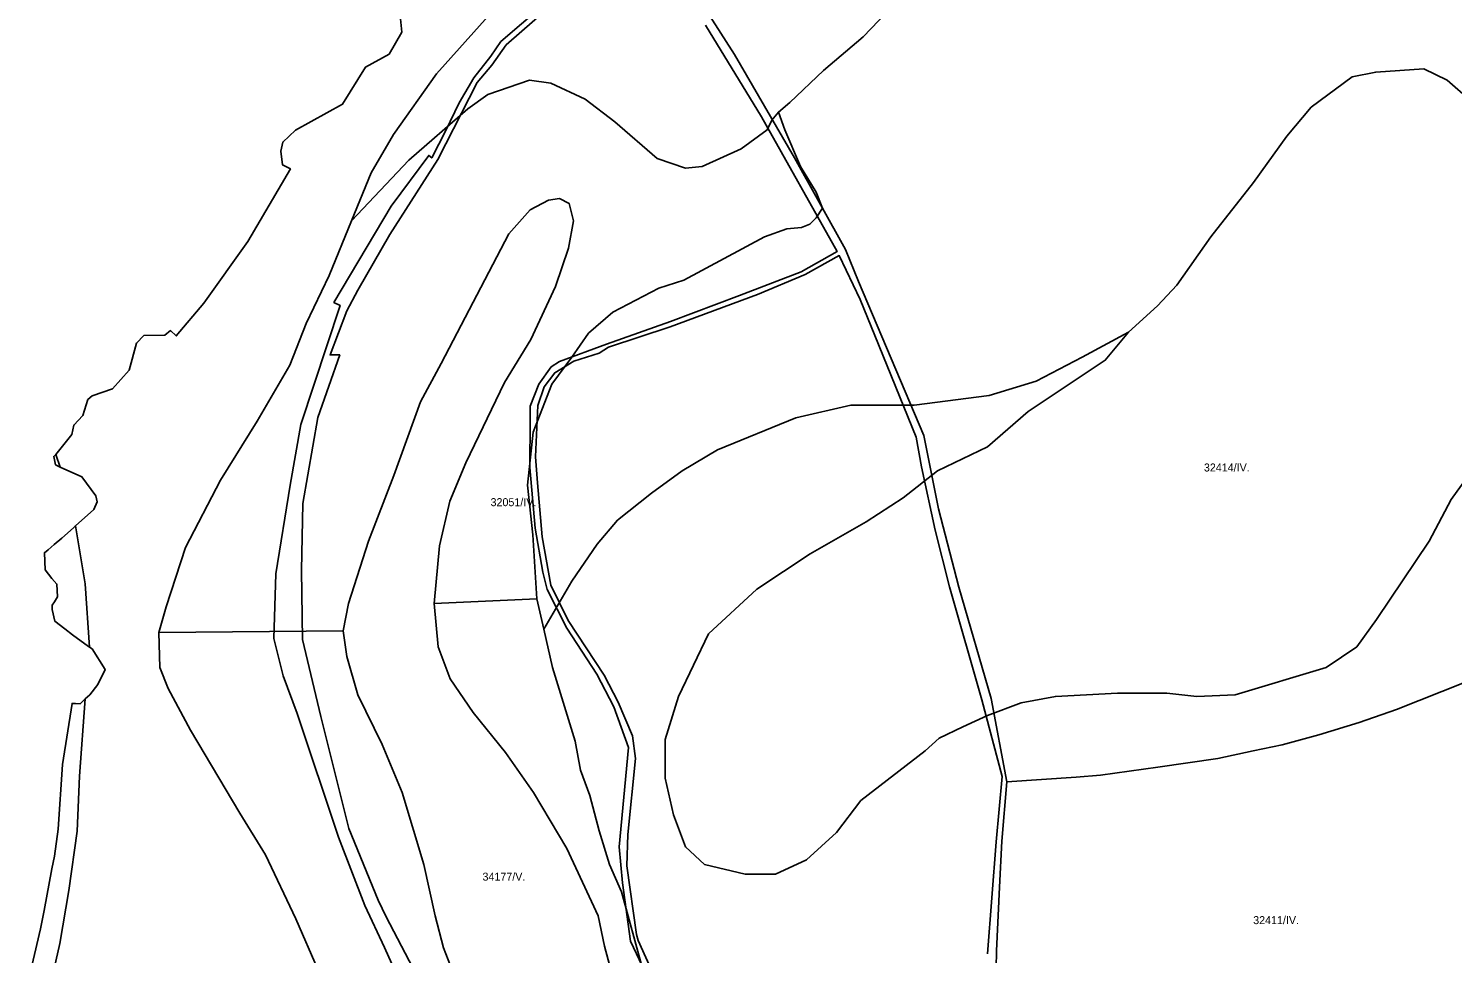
# Model space of a CAD drawing. Extents: x -532083 to -529270, y -1180561 to -1176456.
# Drawn here: x -532029 to -531139, y -1177920 to -1177342 of the extents above; entities that cross this region are included whole.
import ezdxf

# ---------------------------------------------------------------- set-up
doc = ezdxf.new("R2010")
doc.units = 0
for name, color, linetype in [('95560013', 7, 'Continuous'), ('95610013', 7, 'Continuous'), ('95660013', 7, 'Continuous')]:
    doc.layers.add(name, color=color, linetype=linetype)

msp = doc.modelspace()

# ---------------------------------------------------------------- linework, layer by layer
at = {"layer": '95560013'}
for points in [[(-531118.2913, -1177744.82245), (-531146.1423, -1177755.99745), (-531174.2873, -1177767.17245), (-531197.7413, -1177775.40645), (-531222.9543, -1177783.05245), (-531245.8213, -1177789.22745), (-531263.9983, -1177793.05045), (-531285.9863, -1177797.75545), (-531323.4343, -1177803.10345), (-531359.4253, -1177808.17745), (-531374.6003, -1177809.54345), (-531417.7903, -1177812.47045), (-531427.6483, -1177760.34245), (-531447.9583, -1177690.85545), (-531460.6533, -1177641.74245), (-531469.7043, -1177596.00345), (-531510.4973, -1177499.76545), (-531518.6553, -1177479.79745), (-531550.5493, -1177422.47345), (-531588.0313, -1177358.07445), (-531610.2983, -1177323.08245)], [(-532019.5363, -1177957.43845), (-532009.5583, -1177913.42645), (-532004.0573, -1177880.31745), (-531998.8613, -1177843.22345), (-531997.3333, -1177808.88745), (-531993.8613, -1177760.60945), (-531990.9163, -1177758.09745), (-531985.9083, -1177751.59745), (-531981.3223, -1177742.26745), (-531989.5113, -1177729.19145), (-531991.0143, -1177728.18545), (-531993.8163, -1177688.61945), (-531999.9123, -1177652.38745), (-531988.2743, -1177642.14645), (-531986.3353, -1177637.53845), (-531987.0493, -1177633.64745), (-531995.8293, -1177621.87045), (-532009.3043, -1177615.72645), (-532012.1683, -1177607.98245), (-532002.1733, -1177595.40845), (-532000.9033, -1177589.51945), (-531995.1923, -1177583.47145), (-531992.0183, -1177573.60245), (-531989.3213, -1177571.21545), (-531976.6283, -1177566.75845), (-531966.3153, -1177555.13945), (-531961.7143, -1177538.26845), (-531957.0913, -1177533.56345), (-531944.0663, -1177533.35645), (-531940.5523, -1177530.45245), (-531936.8303, -1177533.77045), (-531919.6713, -1177513.44645), (-531892.1753, -1177474.87245), (-531865.5833, -1177429.45545), (-531870.4603, -1177426.93945), (-531871.4353, -1177418.41245), (-531870.3203, -1177412.68145), (-531862.3783, -1177405.27345), (-531832.9763, -1177389.05845), (-531818.7133, -1177365.89545), (-531803.8683, -1177357.70445), (-531795.8883, -1177344.11545), (-531797.3733, -1177329.40945)], [(-531708.2143, -1177327.75645), (-531734.1213, -1177349.90345), (-531740.3033, -1177359.05845), (-531750.9023, -1177372.64245), (-531760.0283, -1177388.29345), (-531768.4843, -1177405.48845), (-531777.1983, -1177422.58145), (-531779.1343, -1177421.02745), (-531802.5663, -1177452.68945), (-531838.3183, -1177512.88145), (-531834.5093, -1177514.79145), (-531859.0233, -1177589.12945), (-531865.6003, -1177627.13945), (-531874.6823, -1177682.42745), (-531875.9923, -1177722.74045), (-531870.1533, -1177746.16945), (-531861.2673, -1177769.59845), (-531835.4083, -1177846.99045), (-531819.0393, -1177889.54245), (-531806.8203, -1177915.90545), (-531794.8753, -1177942.31245)], [(-531635.6623, -1177939.19145), (-531648.2733, -1177911.52045), (-531649.2633, -1177907.75945), (-531655.3233, -1177864.93045), (-531654.7733, -1177845.31145), (-531649.8143, -1177797.78445), (-531651.7423, -1177783.69245), (-531660.8133, -1177762.54545), (-531669.3843, -1177745.63645), (-531691.9553, -1177711.53245), (-531702.8123, -1177689.46545), (-531708.2413, -1177659.37345), (-531711.1903, -1177625.66645), (-531712.3543, -1177609.32945), (-531710.9963, -1177577.24045), (-531706.9253, -1177565.57145), (-531700.3333, -1177556.81945), (-531688.5053, -1177549.62345), (-531672.6073, -1177544.56745), (-531666.7323, -1177540.80045), (-531628.1693, -1177528.12145), (-531573.7513, -1177507.92045), (-531543.9723, -1177495.45645), (-531522.5473, -1177483.63745), (-531509.4603, -1177511.12445), (-531500.3393, -1177533.48945), (-531474.4973, -1177597.02345), (-531471.2473, -1177615.53345), (-531462.7023, -1177655.07245), (-531453.6053, -1177690.46345), (-531433.5733, -1177761.07545), (-531420.7543, -1177808.97045), (-531424.6003, -1177849.79445), (-531429.9573, -1177919.79245)], [(-531424.5953, -1177928.77945), (-531424.3013, -1177917.87945), (-531422.5393, -1177878.11045), (-531421.0973, -1177849.35345), (-531417.7903, -1177812.47045), (-531374.6003, -1177809.54345), (-531359.4253, -1177808.17745), (-531323.4343, -1177803.10345), (-531285.9863, -1177797.75545), (-531263.9983, -1177793.05045), (-531245.8213, -1177789.22745), (-531222.9543, -1177783.05245), (-531197.7413, -1177775.40645), (-531174.2873, -1177767.17245), (-531146.1423, -1177755.99745), (-531118.2913, -1177744.82245)]]:
    msp.add_lwpolyline(points, dxfattribs=at)
at = {"layer": '95610013'}
for points in [[(-531784.1913, -1177937.69645), (-531805.7253, -1177896.68445), (-531810.6313, -1177886.29445), (-531829.0433, -1177841.54345), (-531846.6013, -1177771.61345), (-531857.9623, -1177723.43945), (-531858.5783, -1177680.29345), (-531857.6733, -1177638.54545), (-531848.3243, -1177584.69645), (-531834.7523, -1177545.67145), (-531840.7843, -1177545.67145), (-531830.2843, -1177518.14145), (-531823.3923, -1177505.30245), (-531803.3723, -1177470.40745), (-531773.5063, -1177423.66045), (-531748.8923, -1177375.59745), (-531739.5843, -1177364.61145), (-531730.7163, -1177351.93545), (-531704.7753, -1177329.25145)], [(-531606.2113, -1177339.70845), (-531571.1533, -1177396.98845), (-531523.8333, -1177481.05845), (-531546.3283, -1177493.73745), (-531584.8923, -1177508.56545), (-531627.9543, -1177524.88045), (-531667.9263, -1177538.86745), (-531697.3633, -1177549.74645), (-531702.6313, -1177553.16445), (-531710.3773, -1177564.04345), (-531715.6453, -1177577.71945), (-531715.6453, -1177586.42245), (-531715.9553, -1177615.94945), (-531712.5463, -1177653.86945), (-531707.7413, -1177681.44645), (-531705.1103, -1177692.22045), (-531692.8353, -1177716.40645), (-531673.9843, -1177745.21045), (-531663.4623, -1177765.43945), (-531654.3013, -1177790.95345), (-531660.0843, -1177852.93545), (-531657.9533, -1177875.52945), (-531653.0833, -1177911.86445), (-531631.1683, -1177958.12845)]]:
    msp.add_lwpolyline(points, dxfattribs=at)
at = {"layer": '95660013'}
for points in [[(-531473.3123, -1177311.00045), (-531507.6253, -1177347.00045), (-531532.3753, -1177368.00045), (-531553.3753, -1177388.00045), (-531560.6253, -1177394.00045), (-531564.6253, -1177399.00045), (-531567.6253, -1177405.00045), (-531583.8123, -1177417.00045), (-531608.3123, -1177428.00045), (-531618.6253, -1177429.00045), (-531636.3753, -1177423.00045), (-531662.8753, -1177400.00045), (-531681.3753, -1177386.00045), (-531702.8753, -1177376.00045), (-531716.1873, -1177374.00045), (-531742.1253, -1177383.00045), (-531754.6873, -1177392.00045), (-531791.6253, -1177424.00045), (-531827.3123, -1177462.00045), (-531815.1253, -1177432.00045), (-531801.1253, -1177408.00045), (-531774.3123, -1177370.00045), (-531741.8753, -1177334.00045)], [(-531127.8753, -1177387.00045), (-531142.6253, -1177374.00045), (-531157.3123, -1177367.00045), (-531187.3753, -1177369.00045), (-531202.1873, -1177372.00045), (-531227.6253, -1177391.00045), (-531243.0003, -1177409.00045), (-531263.8123, -1177438.00045), (-531290.5003, -1177472.00045), (-531311.6253, -1177502.00045), (-531323.6253, -1177515.00045), (-531341.9473, -1177531.51445), (-531370.8123, -1177547.00045), (-531399.6253, -1177562.00045), (-531429.0003, -1177571.00045), (-531475.8753, -1177577.00045), (-531515.3123, -1177577.00045), (-531549.8123, -1177585.00045), (-531598.6253, -1177605.00045), (-531620.8123, -1177618.00045), (-531639.8123, -1177632.00045), (-531661.1873, -1177649.00045), (-531673.8753, -1177664.00045), (-531689.6253, -1177687.00045), (-531707.1873, -1177717.00045), (-531711.5003, -1177698.00045), (-531714.1253, -1177658.00045), (-531717.3753, -1177627.00045), (-531713.8123, -1177594.00045), (-531702.1253, -1177564.00045), (-531689.6253, -1177547.00045), (-531679.1873, -1177532.00045), (-531664.1253, -1177519.00045), (-531635.3753, -1177504.00045), (-531619.6873, -1177499.00045), (-531569.3753, -1177472.00045), (-531555.3123, -1177467.00045), (-531546.1253, -1177466.00045), (-531540.8753, -1177464.00045), (-531537.0003, -1177460.00045), (-531533.1253, -1177454.00045), (-531537.0003, -1177444.00045), (-531546.8123, -1177428.00045), (-531556.6253, -1177405.00045), (-531560.6253, -1177394.00045), (-531553.3753, -1177388.00045), (-531532.3753, -1177368.00045), (-531507.6253, -1177347.00045), (-531473.3123, -1177311.00045)], [(-532029.2073, -1177936.36445), (-532021.7413, -1177904.18045), (-532019.3203, -1177892.84545), (-532014.5413, -1177866.66445), (-532012.9503, -1177858.88545), (-532010.5643, -1177841.93045), (-532007.9793, -1177801.43745), (-532001.9613, -1177763.41645), (-531999.8993, -1177763.41645), (-531996.9543, -1177763.56345), (-531993.8613, -1177760.60945), (-531990.9163, -1177758.09745), (-531985.9083, -1177751.59745), (-531981.3223, -1177742.26745), (-531989.5113, -1177729.19145), (-531991.0143, -1177728.18545), (-531994.0223, -1177726.17445), (-532001.7103, -1177720.47445), (-532006.5563, -1177716.78645), (-532012.7393, -1177712.09245), (-532014.4103, -1177704.71645), (-532014.4103, -1177702.03445), (-532012.9063, -1177699.85445), (-532011.0683, -1177696.83745), (-532011.4493, -1177688.82745), (-532014.7173, -1177685.24245), (-532018.8013, -1177679.91645), (-532019.2093, -1177669.26445), (-532016.8613, -1177667.42045), (-532013.1853, -1177664.14345), (-532008.3863, -1177660.04645), (-532001.1373, -1177653.79845), (-531999.9123, -1177652.38745), (-531988.2743, -1177642.14645), (-531986.3353, -1177637.53845), (-531987.0493, -1177633.64745), (-531995.8293, -1177621.87045), (-532009.3043, -1177615.72645), (-532012.2643, -1177614.29245), (-532013.3873, -1177609.06945), (-532012.1683, -1177607.98245), (-532002.1733, -1177595.40845), (-532000.9033, -1177589.51945), (-531995.1923, -1177583.47145), (-531992.0183, -1177573.60245), (-531989.3213, -1177571.21545), (-531976.6283, -1177566.75845), (-531966.3153, -1177555.13945), (-531961.7143, -1177538.26845), (-531957.0913, -1177533.56345), (-531944.0663, -1177533.35645), (-531940.5523, -1177530.45245), (-531936.8303, -1177533.77045), (-531919.6713, -1177513.44645), (-531892.1753, -1177474.87245), (-531865.5833, -1177429.45545), (-531870.4603, -1177426.93945), (-531871.4353, -1177418.41245), (-531870.3203, -1177412.68145), (-531862.3783, -1177405.27345), (-531832.9763, -1177389.05845), (-531818.7133, -1177365.89545), (-531803.8683, -1177357.70445), (-531795.8883, -1177344.11545), (-531797.3733, -1177329.40945)], [(-531741.8753, -1177334.00045), (-531774.3123, -1177370.00045), (-531801.1253, -1177408.00045), (-531815.1253, -1177432.00045), (-531827.3123, -1177462.00045), (-531841.3123, -1177496.00045), (-531855.6253, -1177526.00045), (-531865.8123, -1177552.00045), (-531886.3753, -1177587.00045), (-531909.3123, -1177624.00045), (-531931.1253, -1177666.00045), (-531943.1873, -1177703.00045), (-531947.8123, -1177719.00045), (-531947.1253, -1177741.00045), (-531941.8753, -1177754.00045), (-531927.8753, -1177780.00045), (-531897.1253, -1177832.00045), (-531881.1253, -1177858.00045), (-531862.1873, -1177898.00045), (-531848.1253, -1177930.00045)], [(-531112.1873, -1177597.00045), (-531140.3123, -1177636.00045), (-531154.0003, -1177662.00045), (-531186.8123, -1177711.00045), (-531199.1253, -1177728.00045), (-531218.3123, -1177741.00045), (-531275.1253, -1177758.00045), (-531299.1873, -1177759.00045), (-531317.8753, -1177757.00045), (-531348.6873, -1177757.00045), (-531387.5003, -1177759.00045), (-531408.8753, -1177763.00045), (-531430.0003, -1177771.00045), (-531445.3753, -1177778.00045), (-531460.1253, -1177785.00045), (-531468.8123, -1177793.00045), (-531509.0003, -1177824.00045), (-531524.3753, -1177844.00045), (-531543.1253, -1177861.00045), (-531562.5003, -1177870.00045), (-531581.3123, -1177870.00045), (-531606.6873, -1177864.00045), (-531618.6873, -1177853.00045), (-531626.1253, -1177833.00045), (-531631.3753, -1177810.00045), (-531631.3753, -1177786.00045), (-531623.1253, -1177759.00045), (-531604.3123, -1177720.00045), (-531574.1873, -1177692.00045), (-531540.8123, -1177670.00045), (-531505.8753, -1177650.00045), (-531482.6253, -1177635.00045), (-531461.1253, -1177618.00045), (-531430.0003, -1177603.00045), (-531404.6253, -1177581.00045), (-531356.3753, -1177549.00045), (-531341.9473, -1177531.51445), (-531323.6253, -1177515.00045), (-531311.6253, -1177502.00045), (-531290.5003, -1177472.00045), (-531263.8123, -1177438.00045), (-531243.0003, -1177409.00045), (-531227.6253, -1177391.00045), (-531202.1873, -1177372.00045), (-531187.3753, -1177369.00045), (-531157.3123, -1177367.00045), (-531142.6253, -1177374.00045), (-531127.8753, -1177387.00045)], [(-531752.3123, -1177961.00045), (-531769.8123, -1177916.00045), (-531775.1253, -1177896.00045), (-531782.1873, -1177864.00045), (-531795.6253, -1177819.00045), (-531808.1253, -1177789.00045), (-531823.5003, -1177758.00045), (-531830.3123, -1177734.00045), (-531832.6253, -1177718.00045), (-531829.3123, -1177701.00045), (-531816.8123, -1177662.00045), (-531801.0003, -1177621.00045), (-531784.1873, -1177575.00045), (-531771.3753, -1177551.00045), (-531729.1253, -1177470.00045), (-531715.6253, -1177455.00045), (-531704.1873, -1177449.00045), (-531697.3753, -1177448.00045), (-531691.3753, -1177451.00045), (-531688.6873, -1177462.00045), (-531691.8123, -1177479.00045), (-531699.8123, -1177503.00045), (-531715.3123, -1177536.00045), (-531731.8123, -1177563.00045), (-531755.8753, -1177613.00045), (-531766.0003, -1177637.00045), (-531772.3753, -1177665.00045), (-531775.8123, -1177701.00045), (-531773.1253, -1177728.00045), (-531765.6873, -1177748.00045), (-531751.3123, -1177769.00045), (-531731.1253, -1177794.00045), (-531713.6253, -1177819.00045), (-531692.8123, -1177854.00045), (-531673.3123, -1177896.00045), (-531669.1873, -1177915.00045), (-531661.8123, -1177943.00045)], [(-531645.5003, -1177929.00045), (-531658.6253, -1177881.00045), (-531666.1253, -1177864.00045), (-531672.6253, -1177843.00045), (-531678.5003, -1177821.00045), (-531684.3753, -1177805.00045), (-531687.6873, -1177787.00045), (-531701.6873, -1177741.00045), (-531707.1873, -1177717.00045), (-531689.6253, -1177687.00045), (-531673.8753, -1177664.00045), (-531661.1873, -1177649.00045), (-531639.8123, -1177632.00045), (-531620.8123, -1177618.00045), (-531598.6253, -1177605.00045), (-531549.8123, -1177585.00045), (-531515.3123, -1177577.00045), (-531475.8753, -1177577.00045), (-531429.0003, -1177571.00045), (-531399.6253, -1177562.00045), (-531370.8123, -1177547.00045), (-531341.9473, -1177531.51445), (-531356.3753, -1177549.00045), (-531404.6253, -1177581.00045), (-531430.0003, -1177603.00045), (-531461.1253, -1177618.00045), (-531482.6253, -1177635.00045), (-531505.8753, -1177650.00045), (-531540.8123, -1177670.00045), (-531574.1873, -1177692.00045), (-531604.3123, -1177720.00045), (-531623.1253, -1177759.00045), (-531631.3753, -1177786.00045), (-531631.3753, -1177810.00045), (-531626.1253, -1177833.00045), (-531618.6873, -1177853.00045), (-531606.6873, -1177864.00045), (-531581.3123, -1177870.00045), (-531562.5003, -1177870.00045), (-531543.1253, -1177861.00045), (-531524.3753, -1177844.00045), (-531509.0003, -1177824.00045), (-531468.8123, -1177793.00045), (-531460.1253, -1177785.00045), (-531445.3753, -1177778.00045), (-531430.0003, -1177771.00045), (-531408.8753, -1177763.00045), (-531387.5003, -1177759.00045), (-531348.6873, -1177757.00045), (-531317.8753, -1177757.00045), (-531299.1873, -1177759.00045), (-531275.1253, -1177758.00045), (-531218.3123, -1177741.00045), (-531199.1253, -1177728.00045), (-531186.8123, -1177711.00045), (-531154.0003, -1177662.00045), (-531140.3123, -1177636.00045), (-531112.1873, -1177597.00045)], [(-531661.8123, -1177943.00045), (-531669.1873, -1177915.00045), (-531673.3123, -1177896.00045), (-531692.8123, -1177854.00045), (-531713.6253, -1177819.00045), (-531731.1253, -1177794.00045), (-531751.3123, -1177769.00045), (-531765.6873, -1177748.00045), (-531773.1253, -1177728.00045), (-531775.8123, -1177701.00045), (-531711.5003, -1177698.00045), (-531707.1873, -1177717.00045), (-531701.6873, -1177741.00045), (-531687.6873, -1177787.00045), (-531684.3753, -1177805.00045), (-531678.5003, -1177821.00045), (-531672.6253, -1177843.00045), (-531666.1253, -1177864.00045), (-531658.6253, -1177881.00045), (-531645.5003, -1177929.00045)], [(-531848.1253, -1177930.00045), (-531862.1873, -1177898.00045), (-531881.1253, -1177858.00045), (-531897.1253, -1177832.00045), (-531927.8753, -1177780.00045), (-531941.8753, -1177754.00045), (-531947.1253, -1177741.00045), (-531947.8123, -1177719.00045), (-531832.6253, -1177718.00045), (-531830.3123, -1177734.00045), (-531823.5003, -1177758.00045), (-531808.1253, -1177789.00045), (-531795.6253, -1177819.00045), (-531782.1873, -1177864.00045), (-531775.1253, -1177896.00045), (-531769.8123, -1177916.00045), (-531752.3123, -1177961.00045)]]:
    msp.add_lwpolyline(points, dxfattribs=at)
msp.add_lwpolyline([(-531832.6253, -1177718.00045), (-531947.8123, -1177719.00045), (-531943.1873, -1177703.00045), (-531931.1253, -1177666.00045), (-531909.3123, -1177624.00045), (-531886.3753, -1177587.00045), (-531865.8123, -1177552.00045), (-531855.6253, -1177526.00045), (-531841.3123, -1177496.00045), (-531827.3123, -1177462.00045), (-531791.6253, -1177424.00045), (-531754.6873, -1177392.00045), (-531742.1253, -1177383.00045), (-531716.1873, -1177374.00045), (-531702.8753, -1177376.00045), (-531681.3753, -1177386.00045), (-531662.8753, -1177400.00045), (-531636.3753, -1177423.00045), (-531618.6253, -1177429.00045), (-531608.3123, -1177428.00045), (-531583.8123, -1177417.00045), (-531567.6253, -1177405.00045), (-531564.6253, -1177399.00045), (-531560.6253, -1177394.00045), (-531556.6253, -1177405.00045), (-531546.8123, -1177428.00045), (-531537.0003, -1177444.00045), (-531533.1253, -1177454.00045), (-531537.0003, -1177460.00045), (-531540.8753, -1177464.00045), (-531546.1253, -1177466.00045), (-531555.3123, -1177467.00045), (-531569.3753, -1177472.00045), (-531619.6873, -1177499.00045), (-531635.3753, -1177504.00045), (-531664.1253, -1177519.00045), (-531679.1873, -1177532.00045), (-531689.6253, -1177547.00045), (-531702.1253, -1177564.00045), (-531713.8123, -1177594.00045), (-531717.3753, -1177627.00045), (-531714.1253, -1177658.00045), (-531711.5003, -1177698.00045), (-531775.8123, -1177701.00045), (-531772.3753, -1177665.00045), (-531766.0003, -1177637.00045), (-531755.8753, -1177613.00045), (-531731.8123, -1177563.00045), (-531715.3123, -1177536.00045), (-531699.8123, -1177503.00045), (-531691.8123, -1177479.00045), (-531688.6873, -1177462.00045), (-531691.3753, -1177451.00045), (-531697.3753, -1177448.00045), (-531704.1873, -1177449.00045), (-531715.6253, -1177455.00045), (-531729.1253, -1177470.00045), (-531771.3753, -1177551.00045), (-531784.1873, -1177575.00045), (-531801.0003, -1177621.00045), (-531816.8123, -1177662.00045), (-531829.3123, -1177701.00045)], close=True, dxfattribs=at)

# ---------------------------------------------------------------- texts
for s, rotation, p in [('32414/IV.', 359.99999995, (-531294.72488, -1177618.50045)), ('32051/IV.', 360, (-531740.4688, -1177640.16968)), ('34177/V.', 0, (-531745.5003, -1177874.09285)), ('32411/IV.', 359.99999999, (-531263.9277, -1177901.25745))]:
    msp.add_text(s, height=5, rotation=rotation, dxfattribs=at).set_placement(p)

doc.saveas('drawing.dxf')
